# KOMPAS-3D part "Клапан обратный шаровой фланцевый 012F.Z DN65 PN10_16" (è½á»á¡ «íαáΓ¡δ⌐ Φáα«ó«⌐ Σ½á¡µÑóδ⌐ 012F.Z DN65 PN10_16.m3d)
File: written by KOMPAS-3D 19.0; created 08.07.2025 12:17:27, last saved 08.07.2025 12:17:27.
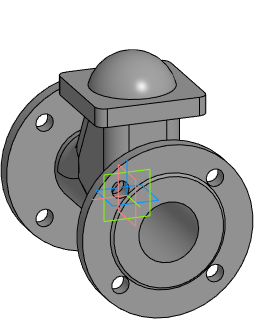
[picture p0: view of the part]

Document properties: Полное имя файла: E:\Dendor Работа Сачек\3D для проектировщиков\5.3 Тип 012F, 012F.Z Клапан обратный шаровой фланцевый\stp_Клапан обратный шаровой фланцевый 012F.Z PN10_16\Клапан обратный шаровой фланцевый 012F.Z DN65 PN10_16.m3d

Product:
- Part/product: Клапан обратный шаровой фланцевый 012F.Z DN65 PN10_16

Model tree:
1. Операция без истории:1  (labels: Клапан обратный шаровой фланцевый 012F.Z DN65 PN10_16)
